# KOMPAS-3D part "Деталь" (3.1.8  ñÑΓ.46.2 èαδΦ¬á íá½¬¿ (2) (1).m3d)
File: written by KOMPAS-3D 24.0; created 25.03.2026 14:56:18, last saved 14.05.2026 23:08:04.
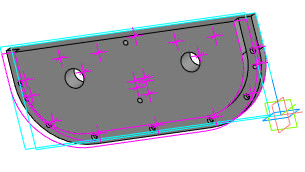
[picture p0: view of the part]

Document properties: Автор: TMK; Полное имя файла: E:\test_kompas\all_v22\3.1.8  дет.46.2 Крышка балки (2) (1).m3d; Организация: TMK

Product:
- Part/product: Деталь
    Масса: 21.934157

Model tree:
1. Операция без истории:1
2. Эскиз:1
3. Смещенная плоскость:1  (with: Грань.Операция без истории:1)
4. Эскиз:2
5. Смещенная плоскость:2  (with: Грань.Операция без истории:1)
6. Эскиз:3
